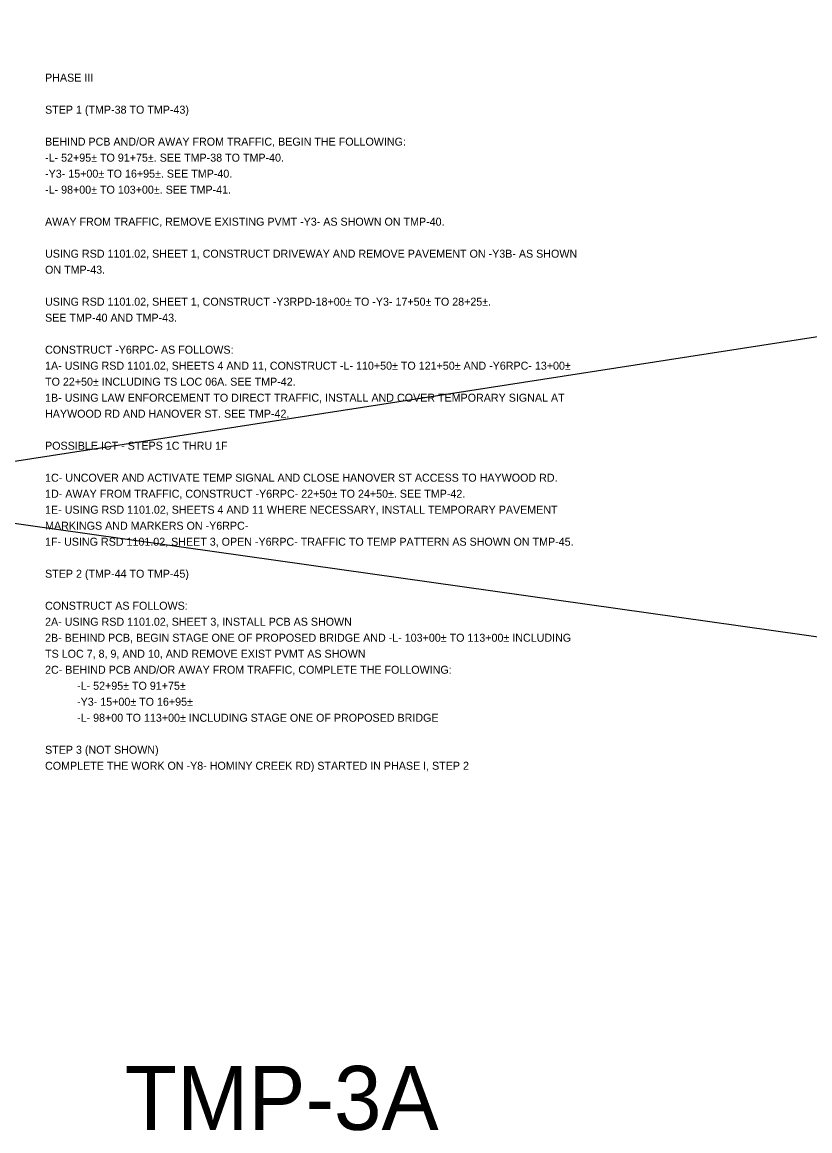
# Model space of a CAD drawing. Extents: x 2483905 to 2494512, y 366160 to 372330.
# Drawn here: x 2490019 to 2490709, y 371326 to 372296 of the extents above; entities that cross this region are included whole.
import ezdxf

# ---------------------------------------------------------------- set-up
doc = ezdxf.new("R2010")
doc.units = 0
doc.layers.add('TC SHEET BORDER LINE THIN', color=7, linetype='Continuous')
doc.layers.add('TC SHEET LAYOUT SHAPE', color=7, linetype='Continuous')

msp = doc.modelspace()

# ---------------------------------------------------------------- linework, layer by layer
at = {"layer": 'TC SHEET BORDER LINE THIN'}
for p, q in [((2486912.05, 372296.36), (2492000.77, 371576.98)), ((2486863.19, 371423.32), (2492035.67, 372226.52))]:
    msp.add_line(p, q, dxfattribs=at)

# ---------------------------------------------------------------- texts
for s, p in [('PHASE III', (2490039.46, 372244.32)), ('STEP 1 (TMP-38 TO TMP-43)', (2490039.46, 372216.32)), ('BEHIND PCB AND/OR AWAY FROM TRAFFIC, BEGIN THE FOLLOWING:', (2490039.46, 372188.32)), ('-L- 52+95± TO 91+75±. SEE TMP-38 TO TMP-40.', (2490039.46, 372174.32)), ('-Y3- 15+00± TO 16+95±. SEE TMP-40.', (2490039.46, 372160.32)), ('-L- 98+00± TO 103+00±. SEE TMP-41.', (2490039.46, 372146.32)), ('AWAY FROM TRAFFIC, REMOVE EXISTING PVMT -Y3- AS SHOWN ON TMP-40.', (2490039.46, 372118.32)), ('USING RSD 1101.02, SHEET 1, CONSTRUCT DRIVEWAY AND REMOVE PAVEMENT ON -Y3B- AS SHOWN ', (2490039.46, 372090.32)), ('ON TMP-43.', (2490039.46, 372076.32)), ('USING RSD 1101.02, SHEET 1, CONSTRUCT -Y3RPD-18+00± TO -Y3- 17+50± TO 28+25±.', (2490039.46, 372048.32)), ('SEE TMP-40 AND TMP-43.', (2490039.46, 372034.32)), ('CONSTRUCT -Y6RPC- AS FOLLOWS:', (2490039.46, 372006.32)), ('1A- USING RSD 1101.02, SHEETS 4 AND 11, CONSTRUCT -L- 110+50± TO 121+50± AND -Y6RPC- 13+00± ', (2490039.46, 371992.32)), ('TO 22+50± INCLUDING TS LOC 06A. SEE TMP-42.', (2490039.46, 371978.32)), ('1B- USING LAW ENFORCEMENT TO DIRECT TRAFFIC, INSTALL AND COVER TEMPORARY SIGNAL AT', (2490039.46, 371964.32)), ('HAYWOOD RD AND HANOVER ST. SEE TMP-42.', (2490039.46, 371950.32)), ('POSSIBLE ICT - STEPS 1C THRU 1F', (2490039.46, 371922.32)), ('1C- UNCOVER AND ACTIVATE TEMP SIGNAL AND CLOSE HANOVER ST ACCESS TO HAYWOOD RD.', (2490039.46, 371894.32)), ('1D- AWAY FROM TRAFFIC, CONSTRUCT -Y6RPC- 22+50± TO 24+50±. SEE TMP-42.', (2490039.46, 371880.32)), ('1E- USING RSD 1101.02, SHEETS 4 AND 11 WHERE NECESSARY, INSTALL TEMPORARY PAVEMENT', (2490039.46, 371866.32)), ('MARKINGS AND MARKERS ON -Y6RPC-', (2490039.46, 371852.32)), ('1F- USING RSD 1101.02, SHEET 3, OPEN -Y6RPC- TRAFFIC TO TEMP PATTERN AS SHOWN ON TMP-45.', (2490039.46, 371838.32)), ('STEP 2 (TMP-44 TO TMP-45)', (2490039.46, 371810.32)), ('CONSTRUCT AS FOLLOWS:', (2490039.46, 371782.32)), ('2A- USING RSD 1101.02, SHEET 3, INSTALL PCB AS SHOWN', (2490039.46, 371768.32)), ('2B- BEHIND PCB, BEGIN STAGE ONE OF PROPOSED BRIDGE AND -L- 103+00± TO 113+00± INCLUDING', (2490039.46, 371754.32)), ('TS LOC 7, 8, 9, AND 10, AND REMOVE EXIST PVMT AS SHOWN', (2490039.46, 371740.32)), ('2C- BEHIND PCB AND/OR AWAY FROM TRAFFIC, COMPLETE THE FOLLOWING:', (2490039.46, 371726.32)), ('-L- 52+95± TO 91+75±', (2490067.46, 371712.32)), ('-Y3- 15+00± TO 16+95±', (2490067.46, 371698.32)), ('-L- 98+00 TO 113+00± INCLUDING STAGE ONE OF PROPOSED BRIDGE', (2490067.46, 371684.32)), ('STEP 3 (NOT SHOWN)', (2490039.46, 371656.32)), ('COMPLETE THE WORK ON -Y8- HOMINY CREEK RD) STARTED IN PHASE I, STEP 2', (2490039.46, 371642.32))]:
    msp.add_text(s, height=7, dxfattribs=at).set_placement(p)
at = {"layer": 'TC SHEET LAYOUT SHAPE'}
msp.add_text('TMP-3A', height=55.996, rotation=0.00008, dxfattribs=at).set_placement((2490109.23, 371327.23))

doc.saveas('drawing.dxf')
